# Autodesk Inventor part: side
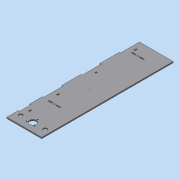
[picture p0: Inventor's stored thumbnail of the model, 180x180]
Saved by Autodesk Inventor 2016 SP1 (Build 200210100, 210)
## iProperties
Created: 2016-06
Part Number: side
Material: Generic
Document SubType Name: Modeling
Designer: Mohamed A.
Density: 1 g/cm^3
Appearance: Default
d0: 85.000 mm
d1: 320.000 mm
d2: 3.000 mm
d3: 0.00 deg
d6: 3.000 mm
d4: 233.000 mm
Author: Mohamed A.
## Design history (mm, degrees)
sketch "Sketch1"
  geometry: L1 (-42.5, 160)-(42.5, 160); L2 (42.5, 160)-(42.5, -160); L3 (42.5, -160)-(-42.5, -160); L4 (-42.5, -160)-(-42.5, 160); L5 (-42.5, 160)-(42.5, -160); L6 (42.5, 160)-(-42.5, -160); 1 further point
  constraints: 12 end point, 2 midpoint, 2 parallel, 1 horizontal, 1 perpendicular
  dimensions: "d0" = 85 distance of L2.end L3.end; "d1" = 320 distance of L1.end L2.end
extrude "Extrusion1" new body sketch "Sketch1" distance "d2" = 3; taper "d3" = 0 deg
sketch "Sketch2"
  geometry: L1 (-26.505, -73)-(-16.505, -73) reference; L2 (-7.505, -76)-(2.495, -76) reference; L3 (42.5, 160)-(-42.5, 160) reference; L4 (-42.5, 113.4)-(-39.5, 113.4); L5 (-39.5, 113.4)-(-39.5, 160); L6 (-42.5, 66.8)-(-39.5, 66.8); L7 (-39.5, 66.8)-(-39.5, 20.2); L8 (-39.5, 20.2)-(-42.5, 20.2); L9 (-39.5, -26.4)-(-42.5, -26.4); L10 (-42.5, -26.4)-(-42.5, -73); L11 (-39.5, 160)-(-42.5, 160); L12 (-42.5, 113.4)-(-42.5, 160); L13 (-42.5, 66.8)-(-42.5, 20.2); L14 (-39.5, -26.4)-(-39.5, -73); L15 (-42.5, -73)-(-39.5, -73); L16 (-42.5, -104)-(-39.5, -104); L17 (-39.5, -104)-(-39.5, -132); L18 (-39.5, -132)-(-42.5, -132); L19 (-42.5, -132)-(-42.5, -104); L20 (-42.5, -160)-(42.5, -160) reference; 1 further point; 1 other entity
  constraints: 32 end point, 6 perpendicular, 5 horizontal, 3 parallel, 2 point on line, 2 vertical, 1 collinear, 2 other
  dimensions: "d4" = 233 distance from line of L3 L1.start (derived); "d6" = 3 distance of L4.start L4.end; "d7" = 46.6 distance between parallel lines of L3 L4 (= 0.2 x d4); "d8" = 3 distance of L6.start L6.end; "d9" = 46.6 distance between parallel lines of L4 L6 (= d7); "d10" = 46.6 distance between parallel lines of L6 L8 (= d7); "d11" = 46.6 distance between parallel lines of L9 L8 (= d10); "d16" = 3 distance of L17.end L18.end; "d17" = 28 distance between parallel lines of L18 L16 (= 0.333333 x d18); "d18" = 84 distance between parallel lines of L20 L2 (derived); "d19" = 28 distance between parallel lines of L16 L2 (= d17); "d20" = 3 distance between parallel lines of L10 L14
extrude "Extrusion2" cut sketch "Sketch2" distance "d12" = 10; taper "d13" = 0 deg
sketch "Sketch3"
  geometry: L1 (-29.5, 142.2)-(-26.5, 142.2); L2 (-26.5, 142.2)-(-26.5, 136.2); L3 (-26.5, 136.2)-(-29.5, 136.2); L4 (-29.5, 136.2)-(-29.5, 142.2); L5 (-29.5, 45.05)-(-26.5, 45.05); L6 (-26.5, 45.05)-(-26.5, 40.5); L7 (-26.5, 40.5)-(-29.5, 40.5); L8 (-29.5, 40.5)-(-29.5, 45.05); L9 (-29.5, -46.7)-(-26.5, -46.7); L10 (-26.5, -46.7)-(-26.5, -52.7); L11 (-26.5, -52.7)-(-29.5, -52.7); L12 (-29.5, -52.7)-(-29.5, -46.7); L13 (-29.5, -115)-(-26.5, -115); L14 (-26.5, -115)-(-26.5, -121); L15 (-26.5, -121)-(-29.5, -121); L16 (-29.5, -121)-(-29.5, -115); L17 (-10.455, 130)-(-13.555, 130) reference; L18 (-10.455, 130)-(-10.455, 127) reference; L19 (-13.555, 127)-(-10.455, 127) reference; L20 (-13.555, 130)-(-13.555, 127) reference; L21 (-10.455, -73)-(-13.555, -73) reference; L22 (-10.455, -73)-(-10.455, -76) reference; L23 (-13.555, -76)-(-10.455, -76) reference; L24 (-13.555, -73)-(-13.555, -76) reference; L25 (-16.505, 130)-(-16.505, 127) reference; L26 (-16.505, 127)-(-26.505, 127) reference; L27 (-26.505, 127)-(-26.505, 130) reference; L28 (-26.505, 130)-(-16.505, 130) reference; L29 (-7.505, 127)-(-7.505, 130) reference; L30 (-7.505, 130)-(2.495, 130) reference; L31 (2.495, 130)-(2.495, 127) reference; L32 (2.495, 127)-(-7.505, 127) reference; L33 (2.495, -73)-(2.495, -76) reference; L34 (2.495, -76)-(-7.505, -76) reference; L35 (-7.505, -76)-(-7.505, -73) reference; L36 (-7.505, -73)-(2.495, -73) reference; L37 (-26.505, -76)-(-26.505, -73) reference; L38 (-26.505, -73)-(-16.505, -73) reference; L39 (-16.505, -73)-(-16.505, -76) reference; L40 (-16.505, -76)-(-26.505, -76) reference; L41 (-21, -118)-(-21, -160) reference; L42 (21, -160)-(21, -118) reference; C1 r 1.4 at (-12.005, 128.5); C2 r 1.4 at (-12.005, -74.5); C3 r 6.3 at (-29.7, -139); C4 r 6.3 at (29.7, -139); C5 r 8.05 at (0, -139) reference; C6 r 8.05 at (0, -139) reference; C7 r 8.5 at (0, -139); C8 r 2 at (0, -127.543) reference; C9 r 2 at (9.922, -144.728) reference; C10 r 2 at (-9.922, -144.728) reference; C11 r 1.4 at (0, -127.543); C12 r 1.4 at (9.922, -144.728); C13 r 1.4 at (-9.922, -144.728); 9 further points
  constraints: 64 end point, 12 horizontal, 8 centre point, 8 parallel, 8 vertical, 4 perpendicular, 3 coincident, 32 other
  dimensions: "d22" = 2.8 diameter of C1; "d23" = 2.8 diameter of C2; "d24" = 12.6 diameter of C3; "d25" = 8.7 distance from line of C3.centre L41; "d26" = 42 distance of L41.start L41.end (derived); "d27" = 21 vertical distance of C3.centre L41.start (= 0.5 x d26); "d28" = 12.6 diameter of C4; "d29" = 21 vertical distance of C4.centre L42.end; "d30" = 8.7 distance from line of L42 C4.centre (= d25); "d32" = 2.8 diameter of C11; "d33" = 2.8 diameter of C12; "d34" = 2.8 diameter of C13; "d35" = 17 diameter of C7
extrude "Extrusion3" cut sketch "Sketch3" distance "d14" = 10; taper "d15" = 0 deg
sketch "Sketch4"
  geometry: 1 further point
body "Solid1"
node "Reference3"
node "Reference4"
node "Reference5"
node "Reference6"
node "Reference7"
node "Reference8"
node "Reference9"
node "Reference10"
node "Reference11"
node "Reference12"
node "Reference13"
